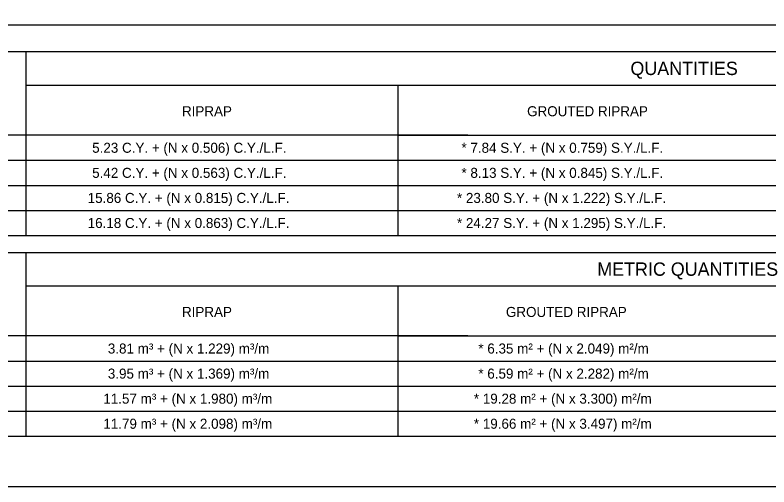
# Model space of a CAD drawing. Extents: x 49991.4 to 50021, y 49987.6 to 50011.4.
# Drawn here: x 50002.571 to 50007.078, y 49987.799 to 49990.622 of the extents above; entities that cross this region are included whole.
import ezdxf

# ---------------------------------------------------------------- set-up
doc = ezdxf.new("R2010")
doc.units = 0
doc.layers.add('Level 1', color=7, linetype='Continuous')
doc.layers.add('Level 2', color=7, linetype='Continuous')

msp = doc.modelspace()

# ---------------------------------------------------------------- linework, layer by layer
at = {"layer": 'Level 1'}
msp.add_line((49999.3835, 49990.5622), (50016.7501, 49990.5622), dxfattribs=at)
msp.add_lwpolyline([(49999.3835, 49998.9992), (50016.7501, 49998.9992), (50016.7501, 49987.7988), (49999.3835, 49987.7988)], close=True, dxfattribs=at)
at = {"layer": 'Level 2'}
for p, q in [((49999.523, 49990.4027), (50010.5707, 49990.4027)), ((50002.6362, 49989.3027), (50002.6362, 49990.4027)), ((50002.6362, 49990.2027), (50010.5707, 49990.2027)), ((50002.6362, 49989.9027), (49999.523, 49989.9027)), ((50005.2768, 49989.9027), (50002.6362, 49989.9027)), ((50004.86, 49989.9027), (50007.2509, 49989.9027)), ((49999.523, 49989.7527), (50007.6678, 49989.7527)), ((49999.523, 49989.6027), (50007.6678, 49989.6027)), ((49999.523, 49989.4527), (50007.6678, 49989.4527)), ((49999.523, 49989.3027), (50007.6678, 49989.3027)), ((49999.523, 49989.2018), (50010.5707, 49989.2018)), ((50002.6362, 49988.1018), (50002.6362, 49989.2018)), ((50002.6362, 49989.0018), (50010.5707, 49989.0018)), ((50002.6362, 49988.7018), (49999.523, 49988.7018)), ((50005.2768, 49988.7018), (50002.6362, 49988.7018)), ((50004.86, 49988.7018), (50007.2509, 49988.7018)), ((49999.523, 49988.5518), (50007.6678, 49988.5518)), ((49999.523, 49988.4018), (50007.6678, 49988.4018)), ((49999.523, 49988.2518), (50007.6678, 49988.2518)), ((49999.523, 49988.1018), (50010.5707, 49988.1018)), ((49999.523, 49988.1018), (50007.6678, 49988.1018))]:
    msp.add_line(p, q, dxfattribs=at)
for points in [[(50004.86, 49990.2027), (50004.86, 49989.3027)], [(50004.86, 49989.0018), (50004.86, 49988.1018)]]:
    msp.add_lwpolyline(points, dxfattribs=at)

# ---------------------------------------------------------------- texts
for s, height, p in [('QUANTITIES', 0.08, (50006.25, 49990.2627)), ('RIPRAP', 0.06, (50003.5686, 49990.0163)), ('GROUTED RIPRAP', 0.06, (50005.6321, 49990.0163)), ('5.23 C.Y. + (N x 0.506) C.Y./L.F.', 0.06, (50003.0317, 49989.7977)), ('* 7.84 S.Y. + (N x 0.759) S.Y./L.F.', 0.06, (50005.2397, 49989.7977)), ('5.42 C.Y. + (N x 0.563) C.Y./L.F.', 0.06, (50003.0317, 49989.6477)), ('* 8.13 S.Y. + (N x 0.845) S.Y./L.F.', 0.06, (50005.2397, 49989.6477)), ('15.86 C.Y. + (N x 0.815) C.Y./L.F.', 0.06, (50003.0048, 49989.4977)), ('* 23.80 S.Y. + (N x 1.222) S.Y./L.F.', 0.06, (50005.2128, 49989.4977)), ('16.18 C.Y. + (N x 0.863) C.Y./L.F.', 0.06, (50003.0048, 49989.3477)), ('* 24.27 S.Y. + (N x 1.295) S.Y./L.F.', 0.06, (50005.2128, 49989.3477)), ('METRIC QUANTITIES', 0.08, (50006.0516, 49989.0618)), ('RIPRAP', 0.06, (50003.5686, 49988.8155)), ('GROUTED RIPRAP', 0.06, (50005.5056, 49988.8155)), ('3.81 m³ + (N x 1.229) m³/m', 0.06, (50003.1253, 49988.5968)), ('* 6.35 m² + (N x 2.049) m²/m', 0.06, (50005.3407, 49988.5968)), ('3.95 m³ + (N x 1.369) m³/m', 0.06, (50003.1253, 49988.4468)), ('* 6.59 m² + (N x 2.282) m²/m', 0.06, (50005.3407, 49988.4468)), ('11.57 m³ + (N x 1.980) m³/m', 0.06, (50003.0984, 49988.2968)), ('* 19.28 m² + (N x 3.300) m²/m', 0.06, (50005.3138, 49988.2968)), ('11.79 m³ + (N x 2.098) m³/m', 0.06, (50003.0984, 49988.1468)), ('* 19.66 m² + (N x 3.497) m²/m', 0.06, (50005.3138, 49988.1468))]:
    msp.add_text(s, height=height, dxfattribs=at).set_placement(p)

doc.saveas('drawing.dxf')
